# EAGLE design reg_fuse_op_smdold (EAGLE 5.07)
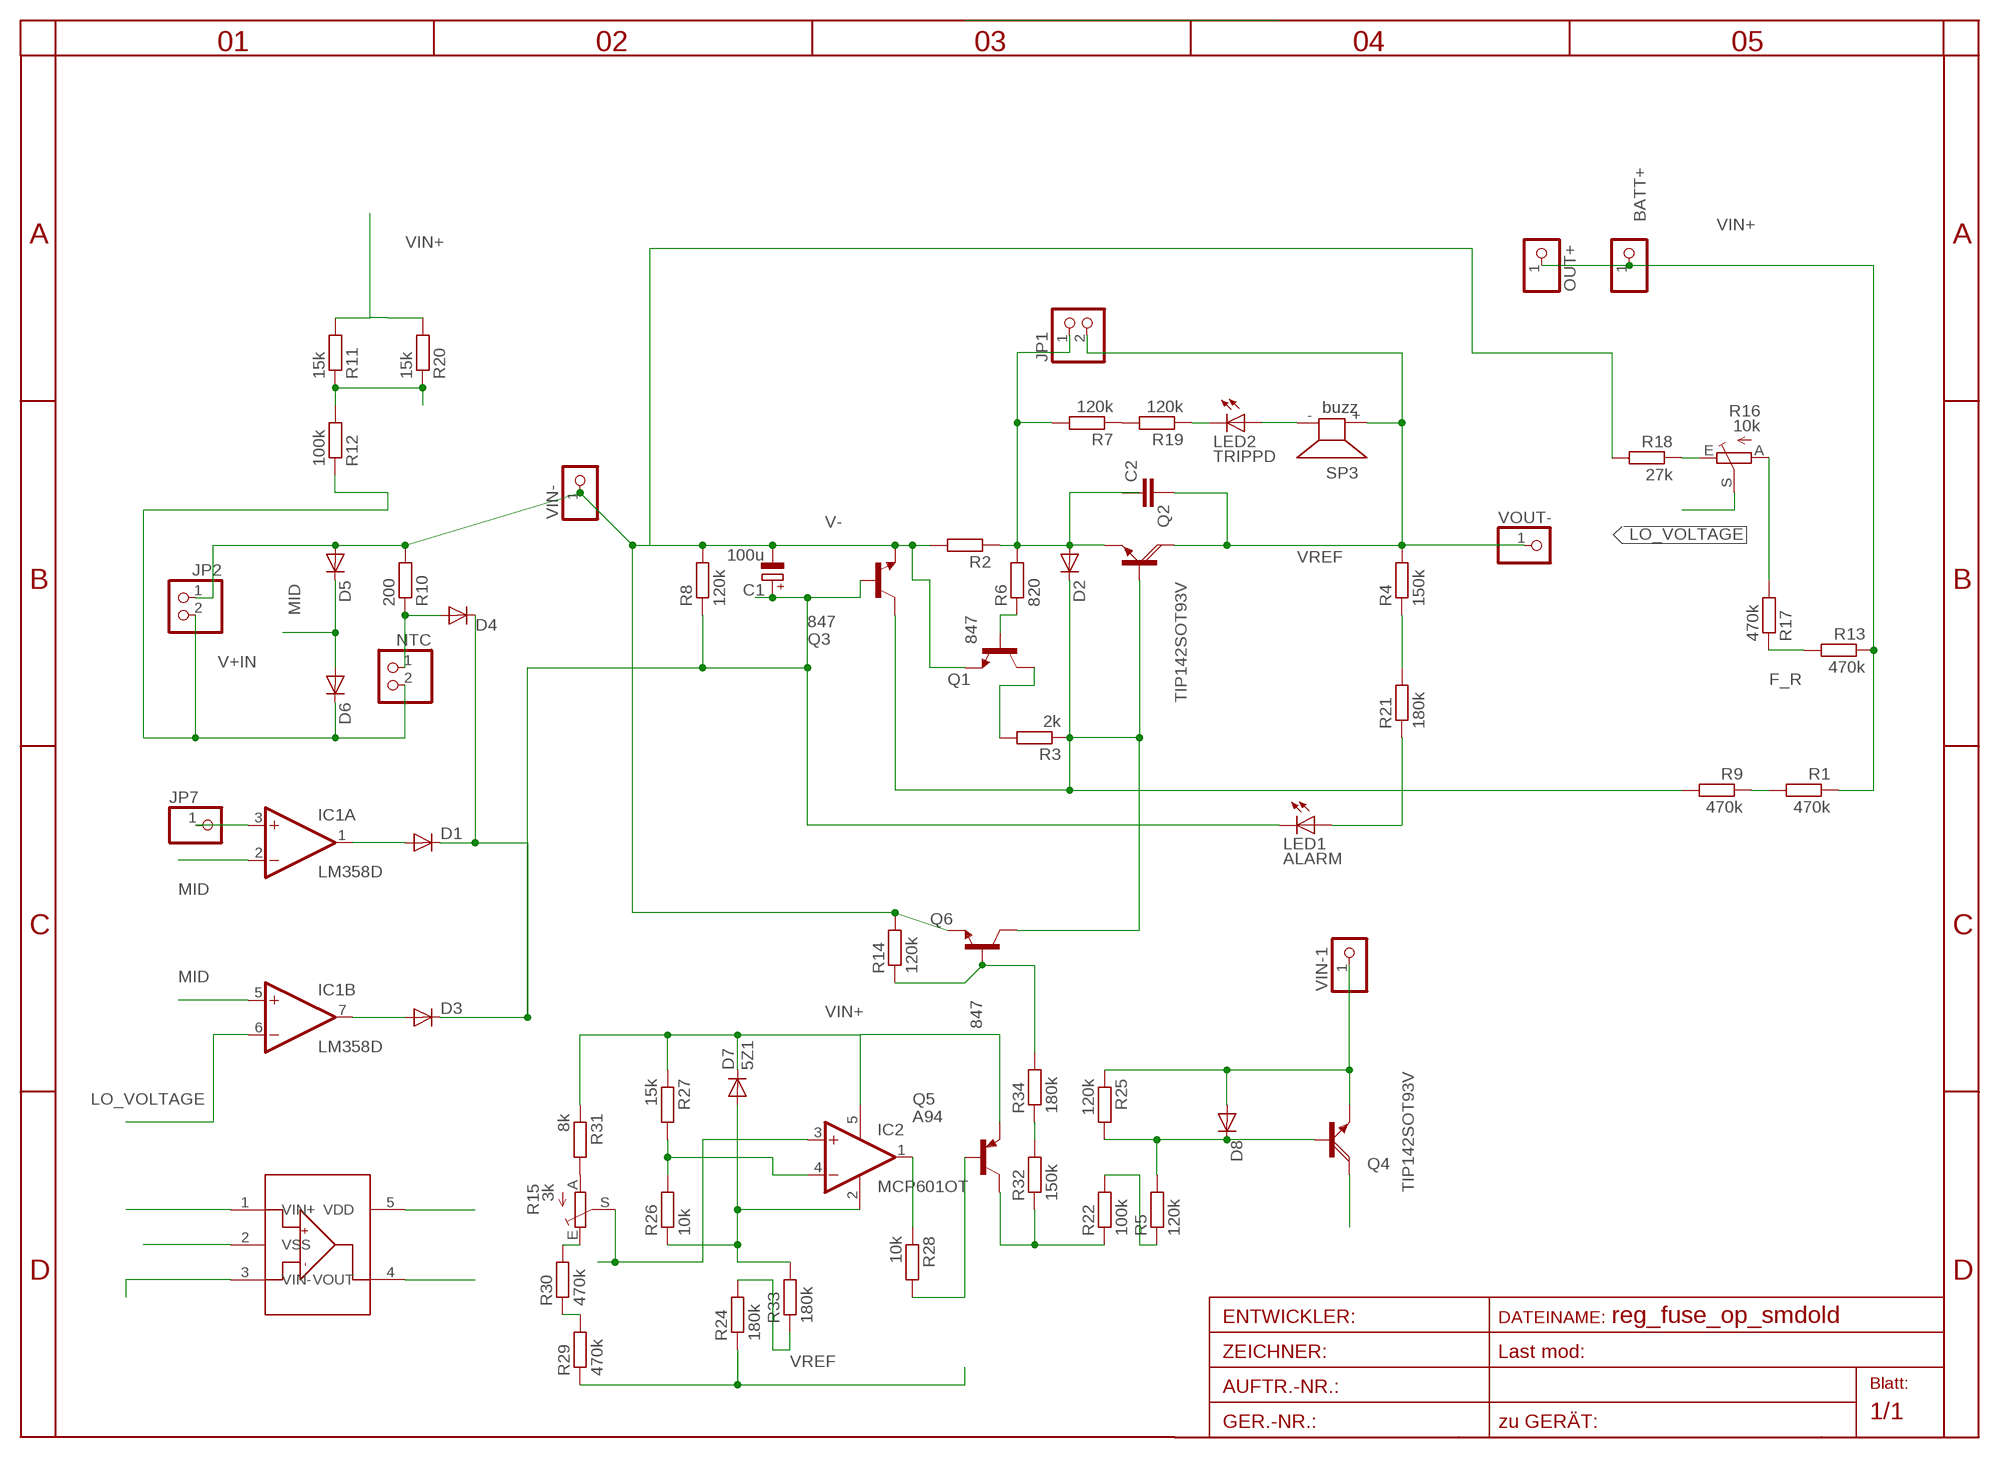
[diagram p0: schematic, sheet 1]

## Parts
BATT+  PINHD-1X12MM3  [1X2MM3]
C1  100u  CPOL-EUE2.5-5  [E2,5-5]
C2  C-EU225-062X268  [C225-062X268]
D1  DIODE-MINIMELF  [MINIMELF]
D2  DIODE-MINIMELF  [MINIMELF]
D3  DIODE-MINIMELF  [MINIMELF]
D4  DIODE-MINIMELF  [MINIMELF]
D5  DIODE-MINIMELF  [MINIMELF]
D6  DIODE-MINIMELF  [MINIMELF]
D7  5Z1  DIODE-MINIMELF  [MINIMELF]
D8  DIODE-MINIMELF  [MINIMELF]
IC1  LM358D  [SO08]
IC2  MCP601OT  [SOT23-5]
JP1  PINHD-1X2/90  [1X02/90]
JP2  V+IN  PINHD-1X2/90  [1X02/90]
JP7  PINHD-1X11X0.4  [1X01]
LED1  ALARM  LED5MM  [LED5MM]
LED2  TRIPPD  LED5MM  [LED5MM]
NTC  PINHD-1X2/90  [1X02/90]
OUT+  PINHD-1X12MM3  [1X2MM3]
Q1  847  BC847ALT1SMD  [SOT23]
Q2  TIP142SOT93V  [SOT93V]
Q3  847  BC847ALT1SMD  [SOT23]
Q4  TIP142SOT93V  [SOT93V]
Q5  A94  MPSA64  [TO92-CBE]
Q6  847  BC847ALT1SMD  [SOT23]
R1  470k  R-EU_R1206  [R1206]
R2  R-EU_0411/12  [0411/12]
R3  2k  R-EU_R0805  [R0805]
R4  150k  R-EU_R1206  [R1206]
R5  120k  R-EU_R1206  [R1206]
R6  820  R-EU_R1206  [R1206]
R7  120k  R-EU_R1206  [R1206]
R8  120k  R-EU_R0805  [R0805]
R9  470k  R-EU_R1206  [R1206]
R10  200  R-EU_R0805  [R0805]
R11  15k  R-EU_R1210  [R1210]
R12  100k  R-EU_0207/12  [0207/12]
R13  470k  R-EU_R1210  [R1210]
R14  120k  R-EU_R0805  [R0805]
R15  3k  TRIM_EU-S64W  [S64W]
R16  10k  TRIM_EU-S64W  [S64W]
R17  470k  R-EU_R1210  [R1210]
R18  27k  R-EU_R1206  [R1206]
R19  120k  R-EU_R1206  [R1206]
R20  15k  R-EU_R1210  [R1210]
R21  180k  R-EU_R1206  [R1206]
R22  100k  R-EU_R1206  [R1206]
R24  180k  R-EU_R1206  [R1206]
R25  120k  R-EU_R0805  [R0805]
R26  10k  R-EU_R1206  [R1206]
R27  15k  R-EU_R0805  [R0805]
R28  10k  R-EU_0207/12  [0207/12]
R29  470k  R-EU_R1206  [R1206]
R30  470k  R-EU_R1206  [R1206]
R31  8k  R-EU_R0805  [R0805]
R32  150k  R-EU_R1206  [R1206]
R33  180k  R-EU_R1206  [R1206]
R34  180k  R-EU_R1206  [R1206]
SP3  buzz  KSS12017MM  [KSS1202]
U$1  MCP6001U  [SOT23-5L]
VIN-  PINHD-1X12MM3  [1X2MM3]
VIN-1  PINHD-1X12MM3  [1X2MM3]
VOUT-  PINHD-1X12MM3  [1X2MM3]

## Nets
E1: D2.A JP1.1 Q2.E R2.1 R6.2 R7.2
F_R: R13.2 R17.1
LO_VOLTAGE: IC1.6(B:-IN) R16.S
MID: D5.C D6.A IC1.2(A:-IN) IC1.5(B:+IN)
N$1: R11.1 R12.2 R20.1
N$2: D3.A IC1.7(B:OUT)
N$3: D1.A IC1.1(A:OUT)
N$4: D2.C Q2.B Q3.3(C) Q6.3(C) R3.1 R9.2
N$5: D8.A Q4.E R25.1 VIN-1.1
N$6: Q1.1(B) R6.1
N$7: Q1.3(C) R3.2
N$8: Q5.B R28.2
N$9: LED2.K(C) R19.1
N$11: LED1.A R21.1
N$12: Q5.C R22.1 R32.1
N$13: LED2.A SP3.-
N$14: R15.A R31.2
N$15: D4.A NTC.1 R10.1
N$17: R16.A R17.2
N$18: R15.E R30.2
N$19: R16.E R18.1
N$20: R1.2 R9.1
N$21: R7.1 R19.2
N$22: R4.1 R21.2
N$23: IC1.3(A:+IN) JP7.1
N$24: D8.C Q4.B R5.2 R25.2
N$26: R29.2 R30.1
N$28: Q6.1(B) R14.1 R34.2
N$29: R24.2 R33.1
N$30: R32.2 R34.1
N$31: R5.1 R22.2
N$33: U$1.4(VOUT)
OP-: D7.A IC2.2(V-) R26.1 R33.2 U$1.2(VSS)
OPINV: IC2.4(-IN) R26.2 R27.2 U$1.3(VIN-)
OPNOI: IC2.3(+IN) R15.S U$1.1(VIN+)
OUT: IC2.1(OUT) R28.1
SIGN: C1.+ D1.C D3.C D4.C LED1.K(C) Q3.1(B) R8.1
V+: D6.C JP2.2 NTC.2 R12.1
V-: C1.- D5.A JP2.1 Q1.2(E) Q3.2(E) Q4.C Q6.2(E) R2.2 R8.2 R10.2 R14.2 R18.2 VIN-.1
VIN+: BATT+.1 D7.C IC2.5(V+) OUT+.1 Q5.E R1.1 R11.2 R13.1 R20.2 R27.1 R31.1 U$1.5(VDD)
VREF: C2.2 JP1.2 Q2.C R4.2 R24.1 R29.1 SP3.+ VOUT-.1
Unconnected: C2.1

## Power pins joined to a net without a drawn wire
V+: IC1.8(P:V+)
V-: IC1.4(P:V-)

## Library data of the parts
BATT+ JP7 OUT+ VIN- VIN-1 VOUT- = pinhead:PINHD-1X1: PIN HEADER
C1 = rcl:CPOL-EU: POLARIZED CAPACITOR, European symbol
C2 = rcl:C-EU: CAPACITOR, European symbol
D1-D8 = diode-1:DIODE-: DIODE
IC1 = linear:LM358: OP AMP also LM158; LM258; LM2904 Source: http://cache.national.com/ds/LM/LM158.pdf
IC2 = linear:MCP601: Single Op Amp 2.7V to 6.0V Single Supply CMOS Source: http://ww1.microchip.com/downloads/en/DeviceDoc/21314g.pdf
JP1 JP2 NTC = pinhead:PINHD-1X2: PIN HEADER
LED1 LED2 = led:LED: LED
Q1 Q3 Q6 = transistor-npn:BC847*: NPN Transistor
Q2 Q4 = transistor-power:TIP142: NPN DARLINGTON TRANSISTOR
Q5 = transistor-pnp:MPSA64*: PNP Transistror
R1-R4 R7-R14 R17-R20 R25 R27 R28 R31 = rcl-2:R-EU_: RESISTOR, European symbol
R5 R6 R21 R22 R24 R26 R29 R30 R32-R34 = rcl:R-EU_: RESISTOR, European symbol
R15 R16 = pot:TRIM_EU-: POTENTIOMETER
SP3 = buzzer:KSS1201: SPEAKER
U$1 = microchip-3:MCP6001U

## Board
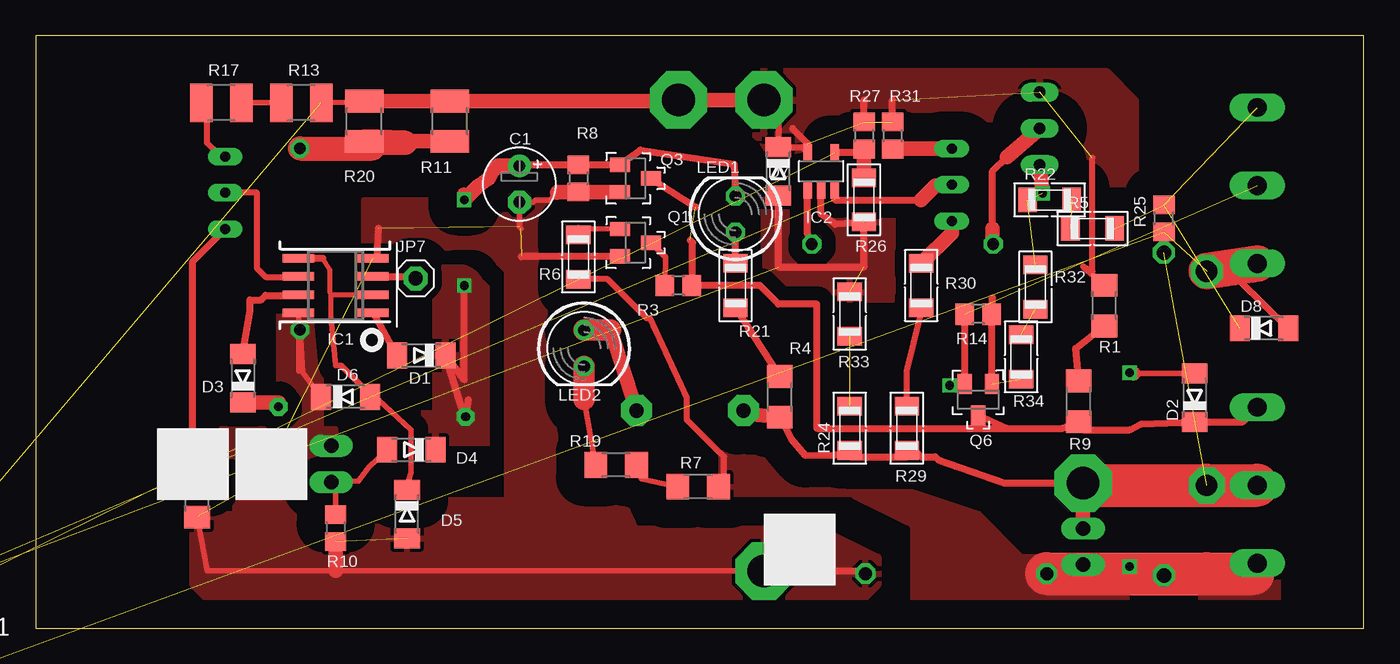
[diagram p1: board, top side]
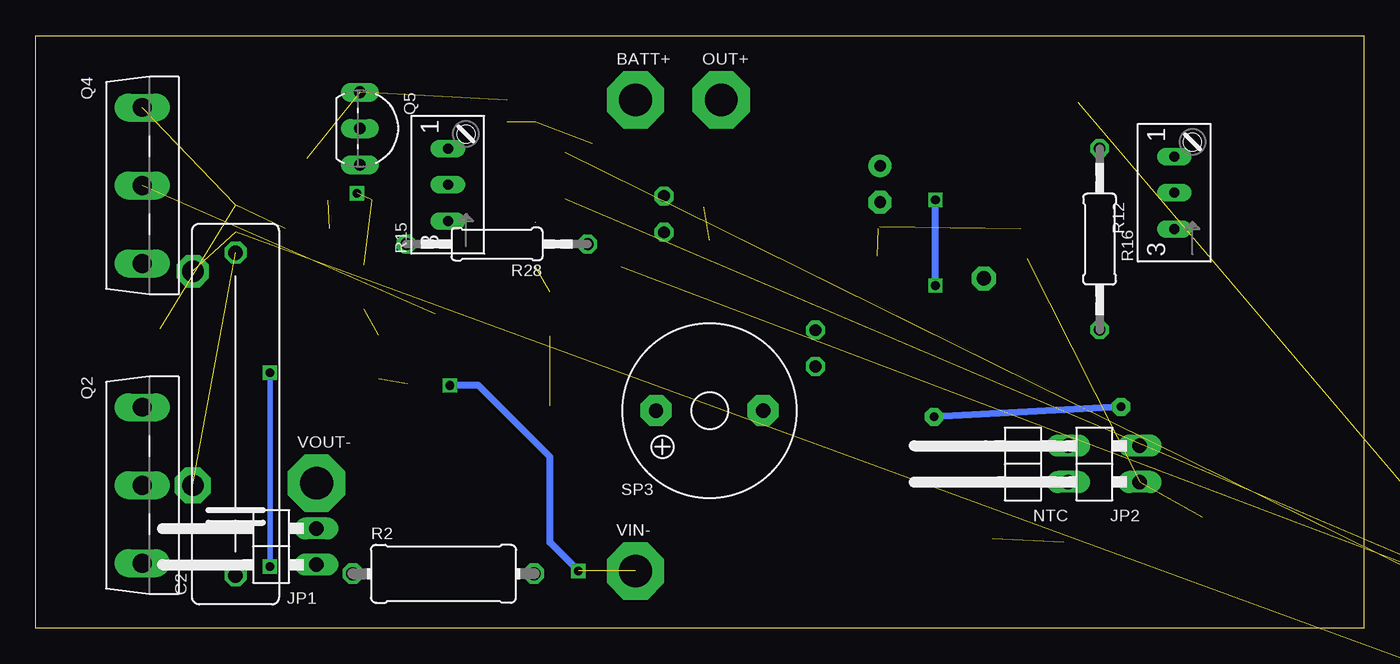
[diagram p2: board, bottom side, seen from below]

Size 93 x 41.5 mm. Coordinates in mm from the lower left corner, seen from the top.
Outline: 0,0 93,0 93,41.5 0,41.5 0,0
Copper layers (1*16): Top 0.035mm / dielectric 1.5mm / Bottom 0.035mm
Design rules "default *": minimum track width 10mil, minimum drill 2mil, track to track 8mil, track to pad 8mil, pad to pad 8mil, via to via 8mil, smd to smd 8mil, copper to edge 40mil, drill to drill 8mil, minimum pad ring 10mil, minimum via ring 8mil, stop-mask expansion 4mil, vias tented up to drill 0mil, thermal gap 10mil

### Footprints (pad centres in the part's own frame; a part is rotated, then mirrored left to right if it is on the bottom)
1X2MM3 = drill 2.3 pad 4 octagon: 1 0,0
E2,5-5 = drill 0.813 pad 1.6 round: + -1.27,0 | drill 0.813 pad 1.6 octagon: - 1.27,0
C225-062X268 = drill 1.016 octagon: 1 -11.303,0; 2 11.303,0
MINIMELF = smd 1.4 x 1.8: A 1.7,0; C -1.7,0
SO08 = smd 0.6 x 2.2: 1 -1.905,-2.6; 2 -0.635,-2.6; 3 0.635,-2.6; 4 1.905,-2.6; 5 1.905,2.6; 6 0.635,2.6; 7 -0.635,2.6; 8 -1.905,2.6
SOT23-5 = smd 0.6 x 1.2: 1 -0.95,-1.306; 2 0,-1.306; 3 0.95,-1.306; 4 0.95,1.306; 5 -0.95,1.306
1X02/90 = drill 1.016 long: 1 -1.27,-3.81; 2 1.27,-3.81
1X01 = drill 1 pad 1.676 octagon: 1 0,0
LED5MM = drill 0.813 octagon: A -1.27,0; K 1.27,0
SOT23 = smd 1 x 1.4: 1 -0.95,-1.1; 2 0.95,-1.1; 3 0,1.1
SOT93V = drill 1.3 pad 1.676 long: B -5.461,-2.54; C 0,-2.54; E 5.461,-2.54
TO92-CBE = drill 0.813 long: B 0,0; C 2.54,0; E -2.54,0
R1206 = smd 1.6 x 1.803: 1 -1.422,0; 2 1.422,0
0411/12 = drill 0.914 octagon: 1 -6.35,0; 2 6.35,0
R0805 = smd 1.3 x 1.5: 1 -0.95,0; 2 0.95,0
R1206' = smd 1.3 x 1.7: 1 -1.55,0; 2 1.55,0
R1210 = smd 1.6 x 2.7: 1 -1.4,0; 2 1.4,0
0207/12 = drill 0.813 octagon: 1 -6.35,0; 2 6.35,0
S64W = drill 0.7 long: A 2.54,1.27; E -2.54,1.27; S 0,1.27
KSS1202 = drill 1 pad 2.159 octagon: + 3.75,0; - -3.75,0
SOT23-5L = smd 0.55 x 1.2: 1 -0.95,-1.3; 2 0,-1.3; 3 0.95,-1.3; 4 0.95,1.3; 5 -0.95,1.3

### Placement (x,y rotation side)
BATT+  51,37 0 bottom
C1  33.87,31.11 270 top
C2  79,15 90 bottom
D1  27,19.1 180 top
D2  81.15,16.14 90 top
D3  14.5,17.5 90 top
D4  26.3,12.5 180 top
D5  26,8 270 top
D6  21.7,16.2 0 top
D7  52,32 270 top
D8  86,21 0 top
IC1  21,24 90 top
IC2  55,32 0 top
JP1  77.15,5.71 90 bottom
JP2  19.5,11.5 90 bottom
JP7  26.6,24.5 0 top
LED1  49,29 90 top
LED2  38.4,19.6 270 top
NTC  24.5,11.5 90 bottom
OUT+  45,37 0 bottom
Q1  42,27 270 top
Q2  83,10 270 bottom
Q3  42,31.5 270 top
Q4  83,31 270 bottom
Q5  70.3,35 270 bottom
Q6  66,16 180 top
R1  74.83,22.59 270 top
R2  64.45,3.81 0 bottom
R3  45,24 180 top
R4  52.1,16.2 270 top
R5  120k  [R1206']  74,28 0 top
R6  820  [R1206']  38,26 270 top
R7  46.38,9.91 0 top
R8  38,31.5 270 top
R9  73.03,15.88 270 top
R10  21,7 270 top
R11  29,35.5 90 top
R12  18.5,27.25 90 bottom
R13  18.6,36.8 180 top
R14  66,22 180 top
R15  62.87,31.06 90 bottom
R16  12,30.5 90 bottom
R17  13,36.8 180 top
R18  11.3,9.2 270 top
R19  40.64,11.43 0 top
R20  23,35.5 90 top
R21  180k  [R1206']  49,24 270 top
R22  100k  [R1206']  71,30 0 top
R24  180k  [R1206']  57,14 90 top
R25  79,28.7 90 top
R26  10k  [R1206']  58,30 90 top
R27  58,34.5 270 top
R28  60.7,26.9 180 bottom
R29  470k  [R1206']  61,14 90 top
R30  470k  [R1206']  62,24 90 top
R31  60,34.5 270 top
R32  150k  [R1206']  70,23.9 270 top
R33  180k  [R1206']  57,22 90 top
R34  180k  [R1206']  69,19 270 top
SP3  45.81,15.24 180 bottom
U$1  not placed on the board
VIN-  51,4 0 bottom
VIN-1  not placed on the board
VOUT-  73.34,10.16 0 bottom

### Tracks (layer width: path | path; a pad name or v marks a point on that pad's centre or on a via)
E1  (via drill 0.6)
  Top 0.4: 76.84,17.84 D2.A | 82,3.81 v76.6,4.3
  Top 0.406: R6.2 40.05,24.45 42.8,21.7 43,21.7 45.6,16.1 45.6,14.6 48.2,12 48.2,10.31 R7.2
  Top 1: R2.1 72.7,3.81 JP1.1 | v76.6,17.9 76.84,17.84
  Top 3: R2.1 82,3.81 85.23,3.81
  Bottom 0.4: v76.6,4.3 v76.6,17.9
  pour Top (isolate 2, rank 2): 48,14 48,8 56,8 58,6 61,2 87,2 87,5 69,5 66,8
F_R
  Top 0.4: R17.1 R13.2
LO_VOLTAGE
  Top 0.406: R16.S 15.5,30.5 15.5,25.2 16.1,24.6 18.36,24.6 IC1.6
MID
  Top 0.35: 20.1,25.9 20.6,25.1 20.6,23.5 20.7,23.4 | 20.7,21.7 20.7,23.4 | IC1.2 20.73,23.36 20.7,23.4
  Top 0.4: D5.C 26,10 26.3,10.9 26.3,13.9 24,16 D6.A 23.1,16.7 21.4,18.4 21,18.4 20.7,21.7
  Top 0.5: 20.1,25.9 IC1.5
N$1
  Top 1: R20.1 R11.1
  Top 1.676: R12.2 23.6,33.6 24,34 25.9,34 R20.1
N$2
  Top 0.5: D3.A 15,22.2 15,23 15.8,23 16.1,23.3 18.34,23.3 IC1.7
N$3
  Top 0.5: IC1.1 23.64,22.13 D1.A
N$4  (1 unrouted)
  Top 0.5: 68,14 54.7,14 54.7,22.7 52,22.7 50.7,24 R3.1 46,24.05 46,27 45.83,27.18 | 68,14 71.91,14 R9.2 73.43,13.87 76.6,13.9 77.39,14.3 D2.C 84.52,14.45 Q2.B | 68,14 Q6.3 | Q3.3 46.21,29.5
  Top 1: Q2.B 85.05,15.45
N$5  (via drill 1.5 pad 2.18)  (2 unrouted)
  Top 0.5: D8.A 84.3,24.3 Q4.E
  Top 2.54: Q4.E v82,25
N$6
  Top 0.4: 38,28 38.9,28 Q1.1
  Top 0.5: R6.1 38,28
N$7
  Top 0.4: R3.2 44.1,26 Q1.3
N$8
  Top 0.5: 67,28 67,32 68,33 | R28.2 67,26.95
  Top 1: 68,33 Q5.B | 67,26.95 67,28
N$9
  Top 0.4: R19.1 38.4,16.01
  Top 1.5: 38.4,16.01 LED2.K
N$11
  Top 0.5: R21.1 LED1.A
N$12  (via drill 0.6)  (2 unrouted)
  Top 1: v70.5,30.46 Q5.C
N$13
  Top 1: SP3.- 40.23,20.87
  Top 1.5: 40.23,20.87 LED2.A
N$14
  Top 1: R15.A 60.05,33.6 R31.2
N$15
  Top 0.4: R10.1 21,9.54 NTC.1 21.23,10.23 22.6,10.3 23.3,11.25 D4.A
N$17
  Top 0.406: R16.A 12.96,33.04 12,34 12,36.4 R17.2
N$18
  Top 0.5: 64.14,28.09 R15.E
  Top 1: 64.14,28.09 64.14,27.69 R30.2
N$19
  Top 0.5: R18.1 11,11.5 11,25.69 R16.E
N$20
  Top 0.5: R9.1 72.83,19.59 R1.2
N$21
  Top 0.4: R19.2 42.43,10.44 R7.1
N$22
  Top 0.5: R4.1 R21.2
N$23
  Top 0.5: IC1.3 26.46,24.64 JP7.1
N$24  (3 unrouted)
N$26
  Top 0.406: R30.1 62,22 61,18 R29.2
N$28  (1 unrouted)
  Top 0.5: 67,23.15 R14.1 Q6.1
N$29  (1 unrouted)
N$30  (1 unrouted)
N$31  (1 unrouted)
OP-  (3 unrouted)
  Top 0.5: D7.A 52,25.3 58,25.3 58,28.4 56,28.3 55,29 IC2.2
  pour Top (isolate 1): 51,30 60,30 60,23 56,23 55,24 51,24
OPINV  (1 unrouted)
  Top 0.5: IC2.4 57.74,33.31 R27.2
  Top 1: R26.2 R27.2
OPNOI  (1 unrouted)
  Top 0.5: IC2.3 55.95,30.05 56,30 62,30 | 64.08,31 R15.S
  Top 1: 62,30 63,31 64.08,31
OUT
  Top 0.5: IC2.1 54.05,27.6 R28.1
SIGN  (via drill 0.6, 0.6 pad 1.27)
  Top 0.5: 17,15.8 v17,15.5 | 30.3,16 v30.1,14.8 29.7,15.8 D1.C 30,17.4 v30,24 | LED1.K 48.9,32.5 42.35,33.5 Q3.1 R8.1 33.94,32.45 C1.+
  Top 1: D3.C 17,15.8 | 30,30.38 v30,30 31,31 31.7,31.5 32,32 32.38,32.38 C1.+
  Bottom 0.5: v30,24 v30,30 | v17,15.5 v30.1,14.8
  pour Top (isolate 1, rank 2): 27,13 32,13 32,26 28,26 28,15 27,15
V+
  Top 0.4: IC1.8 18.4,18 R12.1 18.7,17.9 D6.C
  pour Top (isolate 1, no thermals): 13,14 17,14 17,22 20,22 20,14 21,14 21,12 12,12
V-  (via drill 0.6)  (7 unrouted)
  Top 0.4: R18.2 12,4 21,4 VIN-.1 | 34,28 33.87,28.13 C1.- 34.84,29.84 35,30 36,30 36.5,30.5
  Top 0.5: IC1.4 23.91,25.91 24,28 | R14.2 Q6.2 64.1,17.1 v64,17 | Q1.2 34.05,26.05 34,26 | v55,4 57.91,4 R2.2
  Top 1: Q3.2 R8.2 36.55,30.55 36.5,30.5 | 21,4 R10.2
  Bottom 0.5: v64,17 62,17 57,12 57,6 v55,4
  pour Top (isolate 2): 11,8 14,8 14,10 15,10 16,11 27,11 29,9 33,9 33,25 32,26 23,26 23,30 31,30 32,31 37,31 39,23 37,18 42,7 55,7 59,5 59,3 58,2 12,2 11,3
VIN+  (5 unrouted)
  Top 0.4: R13.1 22.27,36.83 25.93,36.83 R20.2 | 44.9,36.9 OUT+.1
  Top 0.406: R1.1 73.33,25.33 74,25 74,32.94 | BATT+.1 52,36 D7.C 53.66,33.7 IC2.5 | R27.1 58,36 | R31.1 60,36
  Top 0.5: IC2.5 54.05,33.95 53,35 | R27.1 58,37 | 60,36 60,37
  Top 1: R20.2 R11.2 44.9,36.9 | OUT+.1 BATT+.1
  pour Top (isolate 2): 49,39 75,39 77,37 77,30 73,26 71,26 70,27 70,28 72,30 72,34 55,34 54,33 50,33 49,34
VREF  (via drill 1.5 pad 2.54)  (1 unrouted)
  Top 0.5: VOUT-.1 67.84,10.16 63.2,11.8 63,12 62,12 61.55,12.45 R29.1 61,12 60.25,12 60.23,11.98 57,12 R24.1 55.95,12.15 53.9,12.1 52.9,13.28 R4.2
  Top 1: VOUT-.1 JP1.2 | R4.2 50.1,14.98 SP3.+
  Top 3: Q2.C v82,10 73.5,10 VOUT-.1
